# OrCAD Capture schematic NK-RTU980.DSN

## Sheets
1 System Block: size A; title: NK-980mini; rev: 1.0; company: nuvoTon Technology Corp.; note: System Block
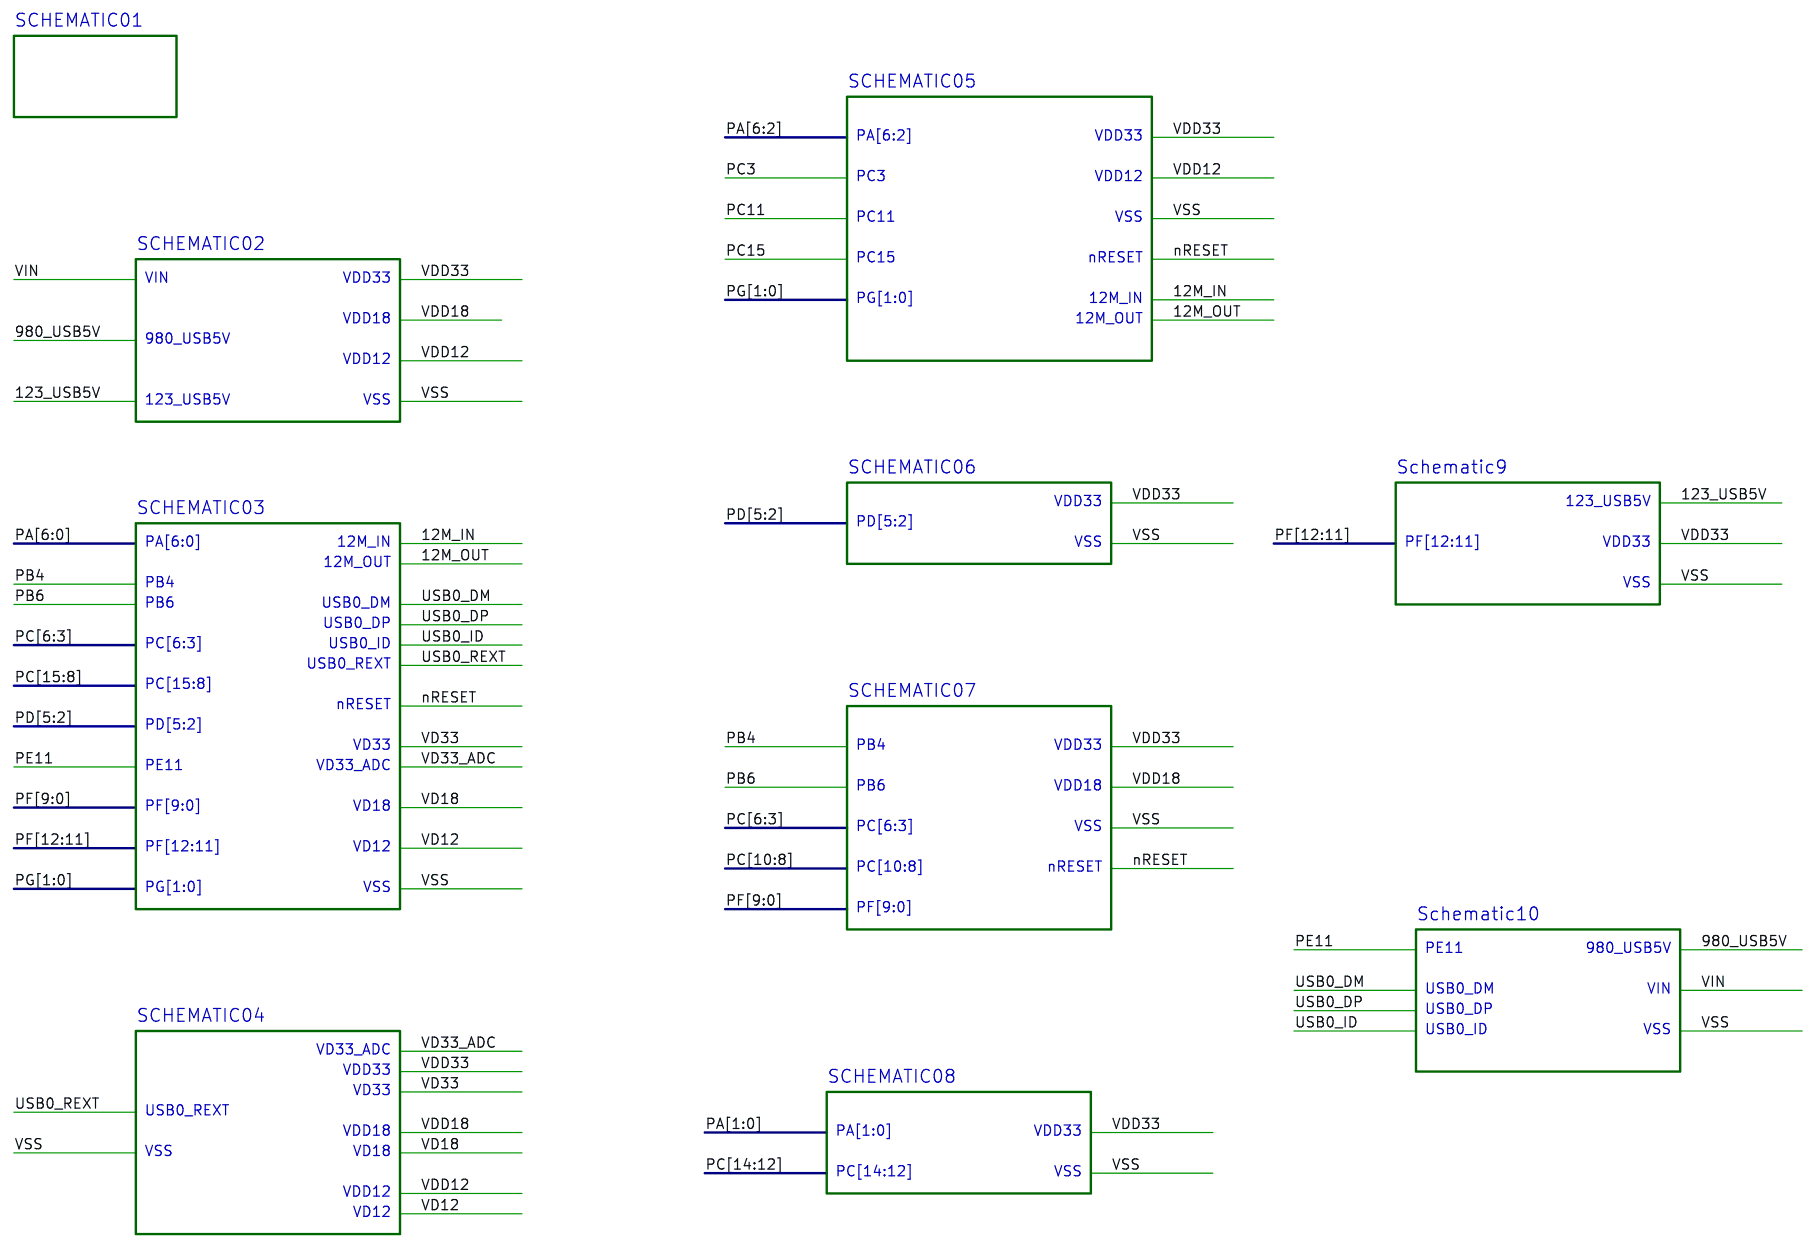
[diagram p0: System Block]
2 NUC980DR: size Custom; note: NUC980DR; block SCHEMATIC03
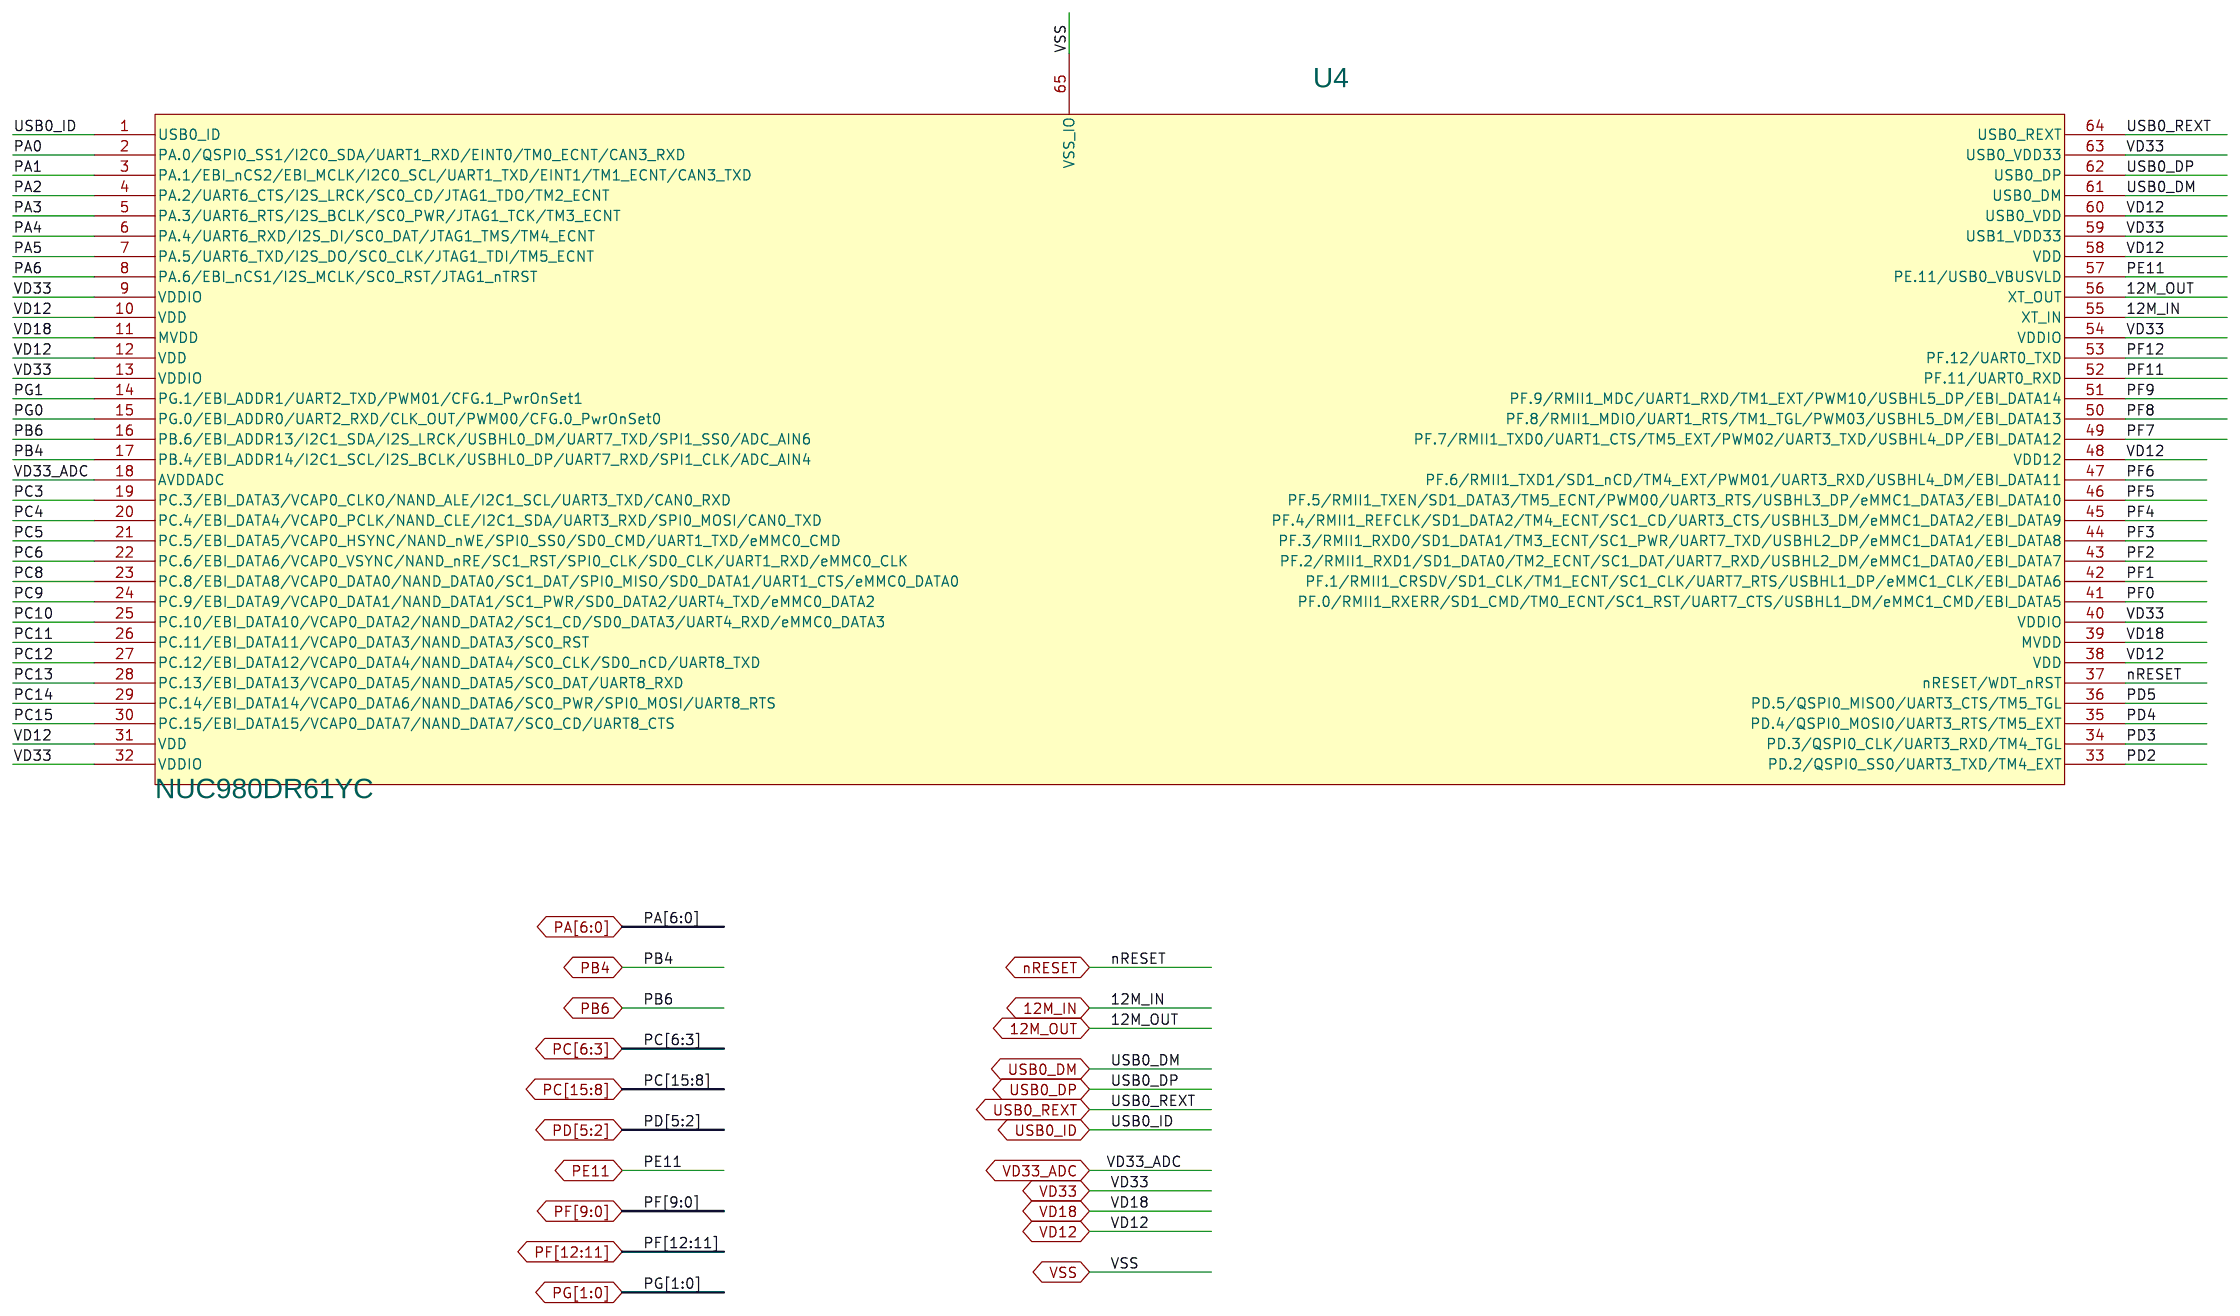
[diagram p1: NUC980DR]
3 NUC123ZD4AN0: size A; note: NUC123ZD4AN0; block Schematic9
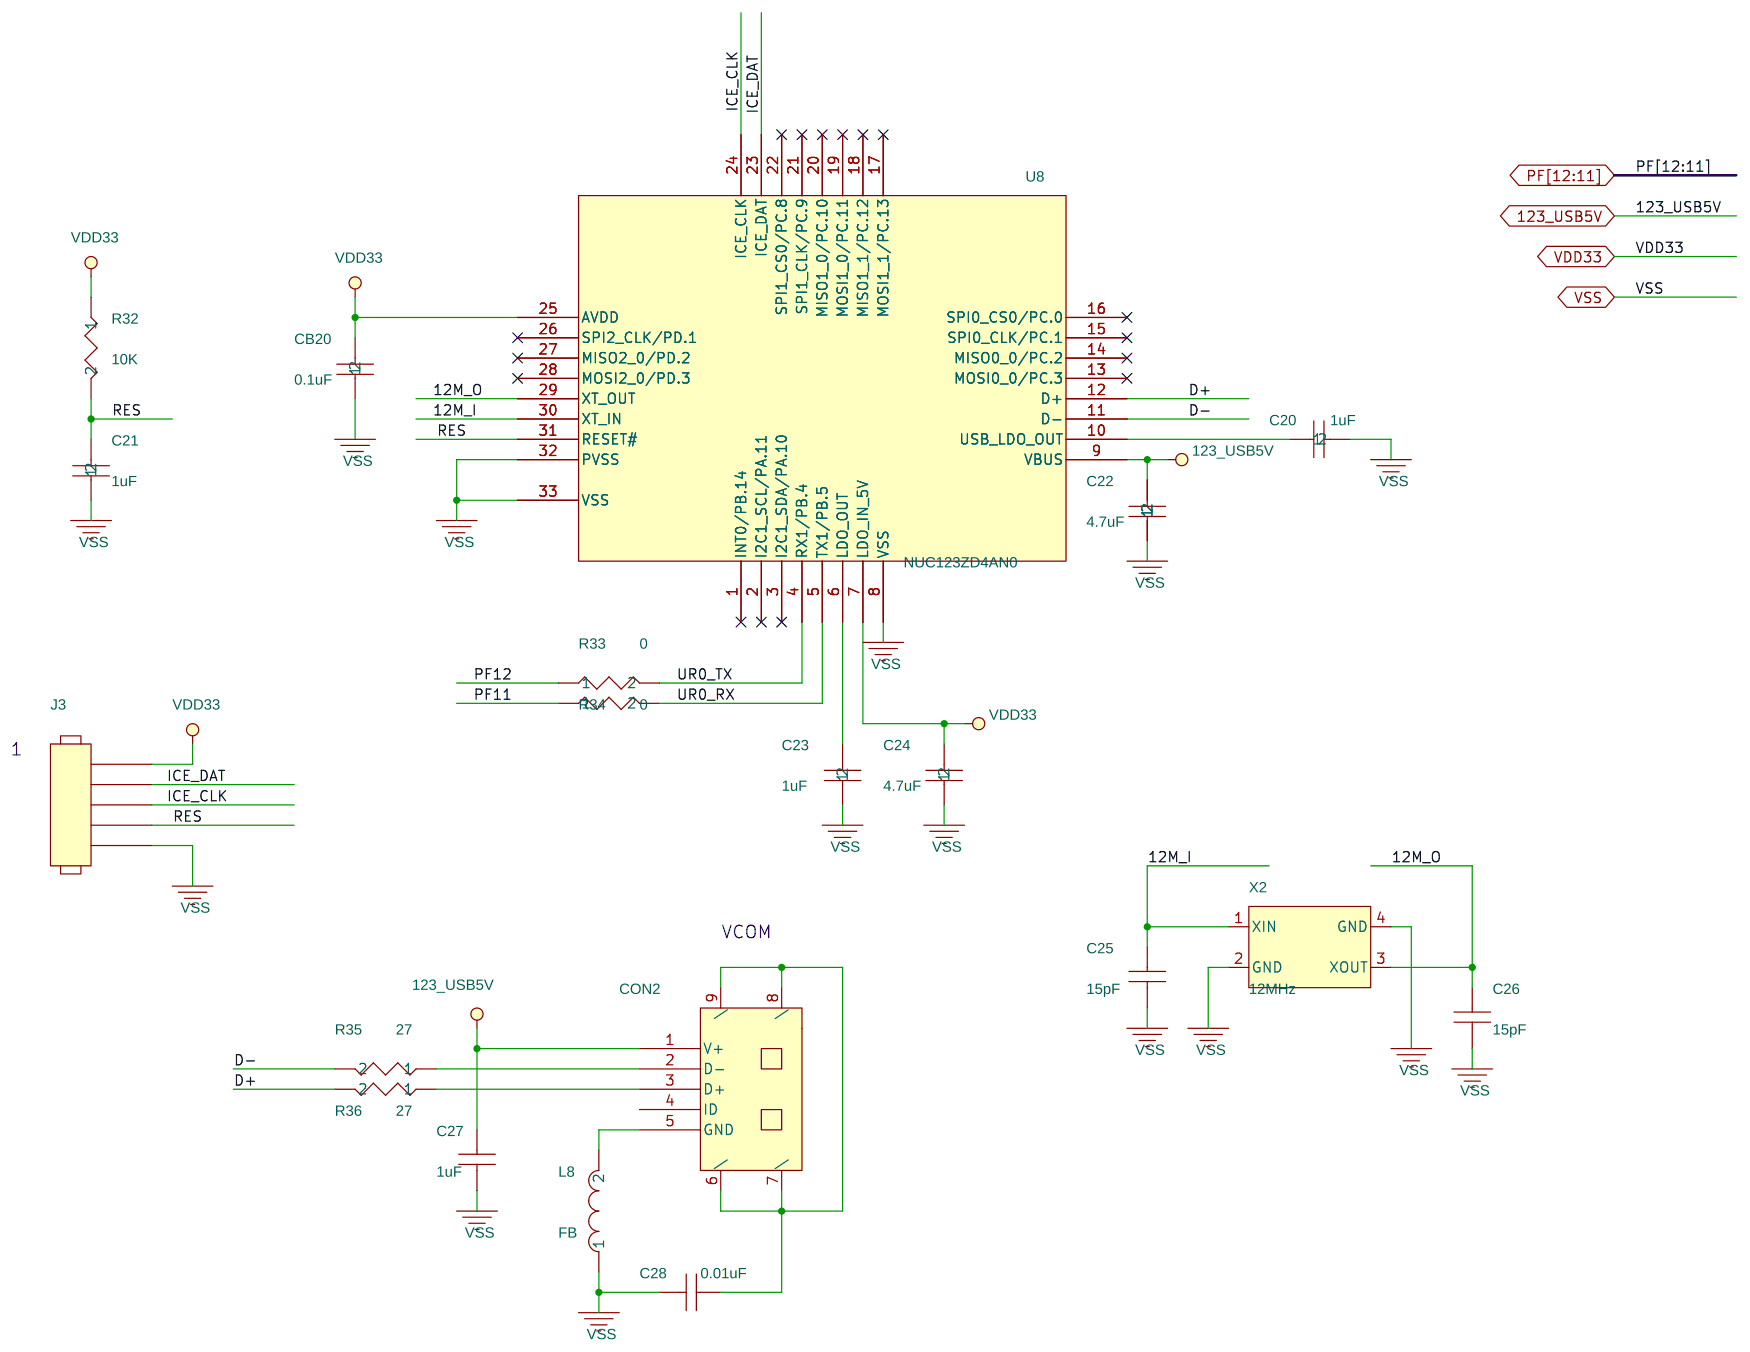
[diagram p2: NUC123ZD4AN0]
4 Setting, ICE, Reset, Debug: size A; note: Setting, ICE, Reset, Debug; block SCHEMATIC05
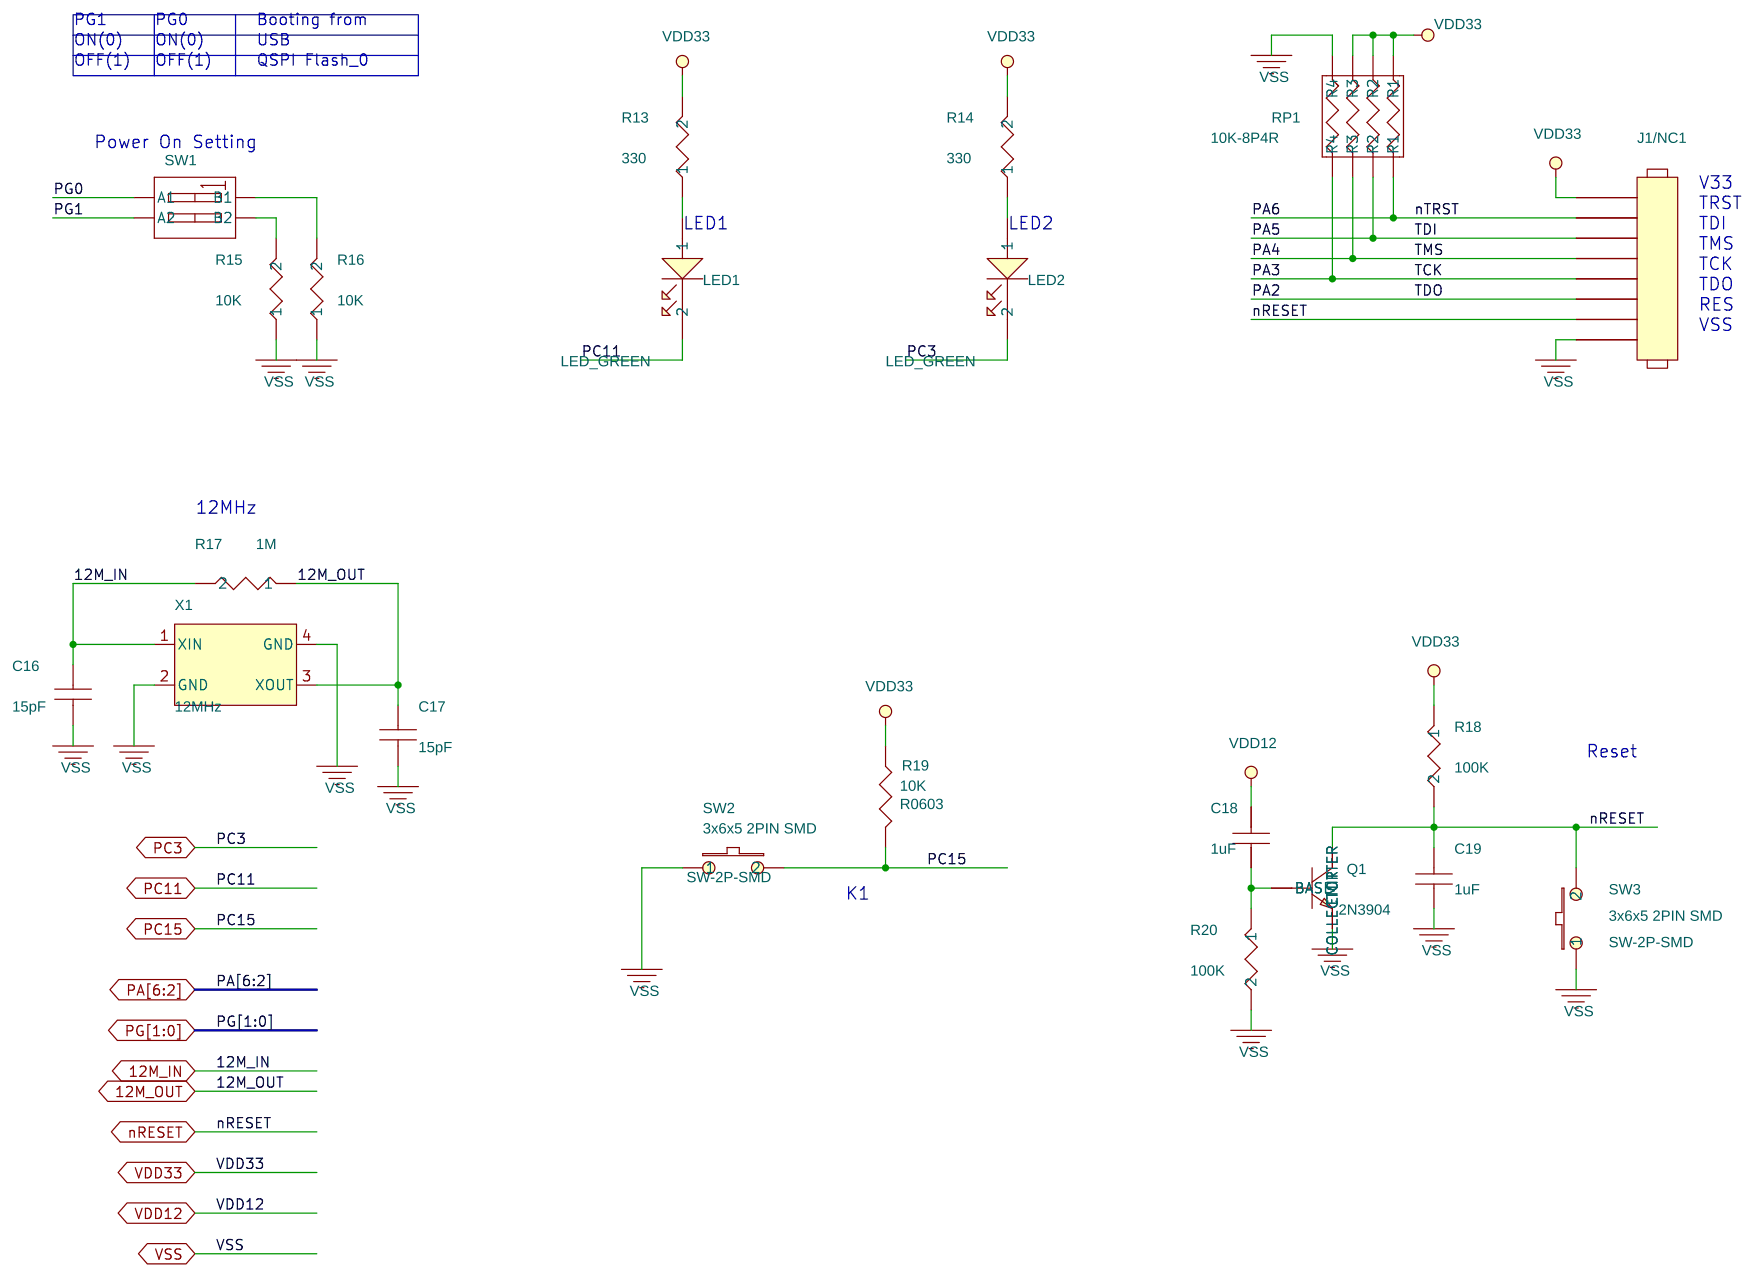
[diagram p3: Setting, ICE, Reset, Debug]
5 USB: size A; note: USB; block Schematic10
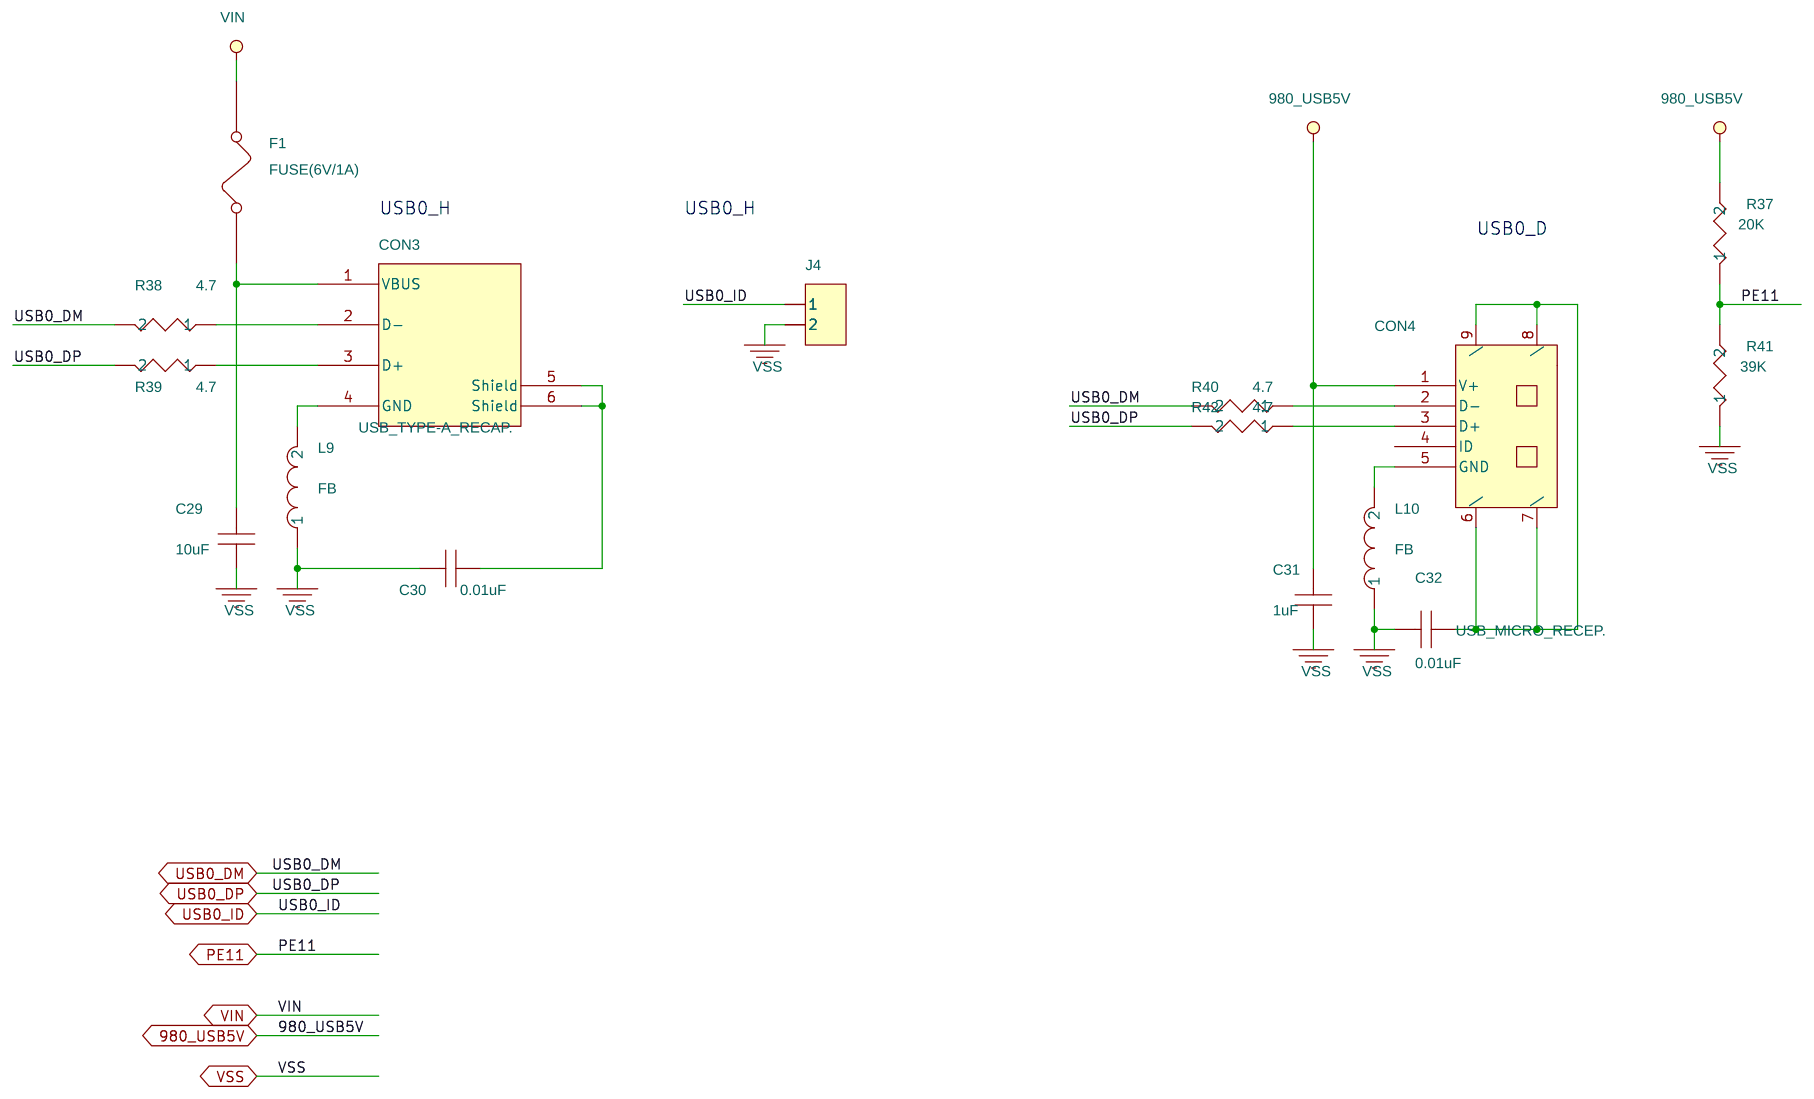
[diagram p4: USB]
6 Power Filter: size A; note: Power Filter; block SCHEMATIC04
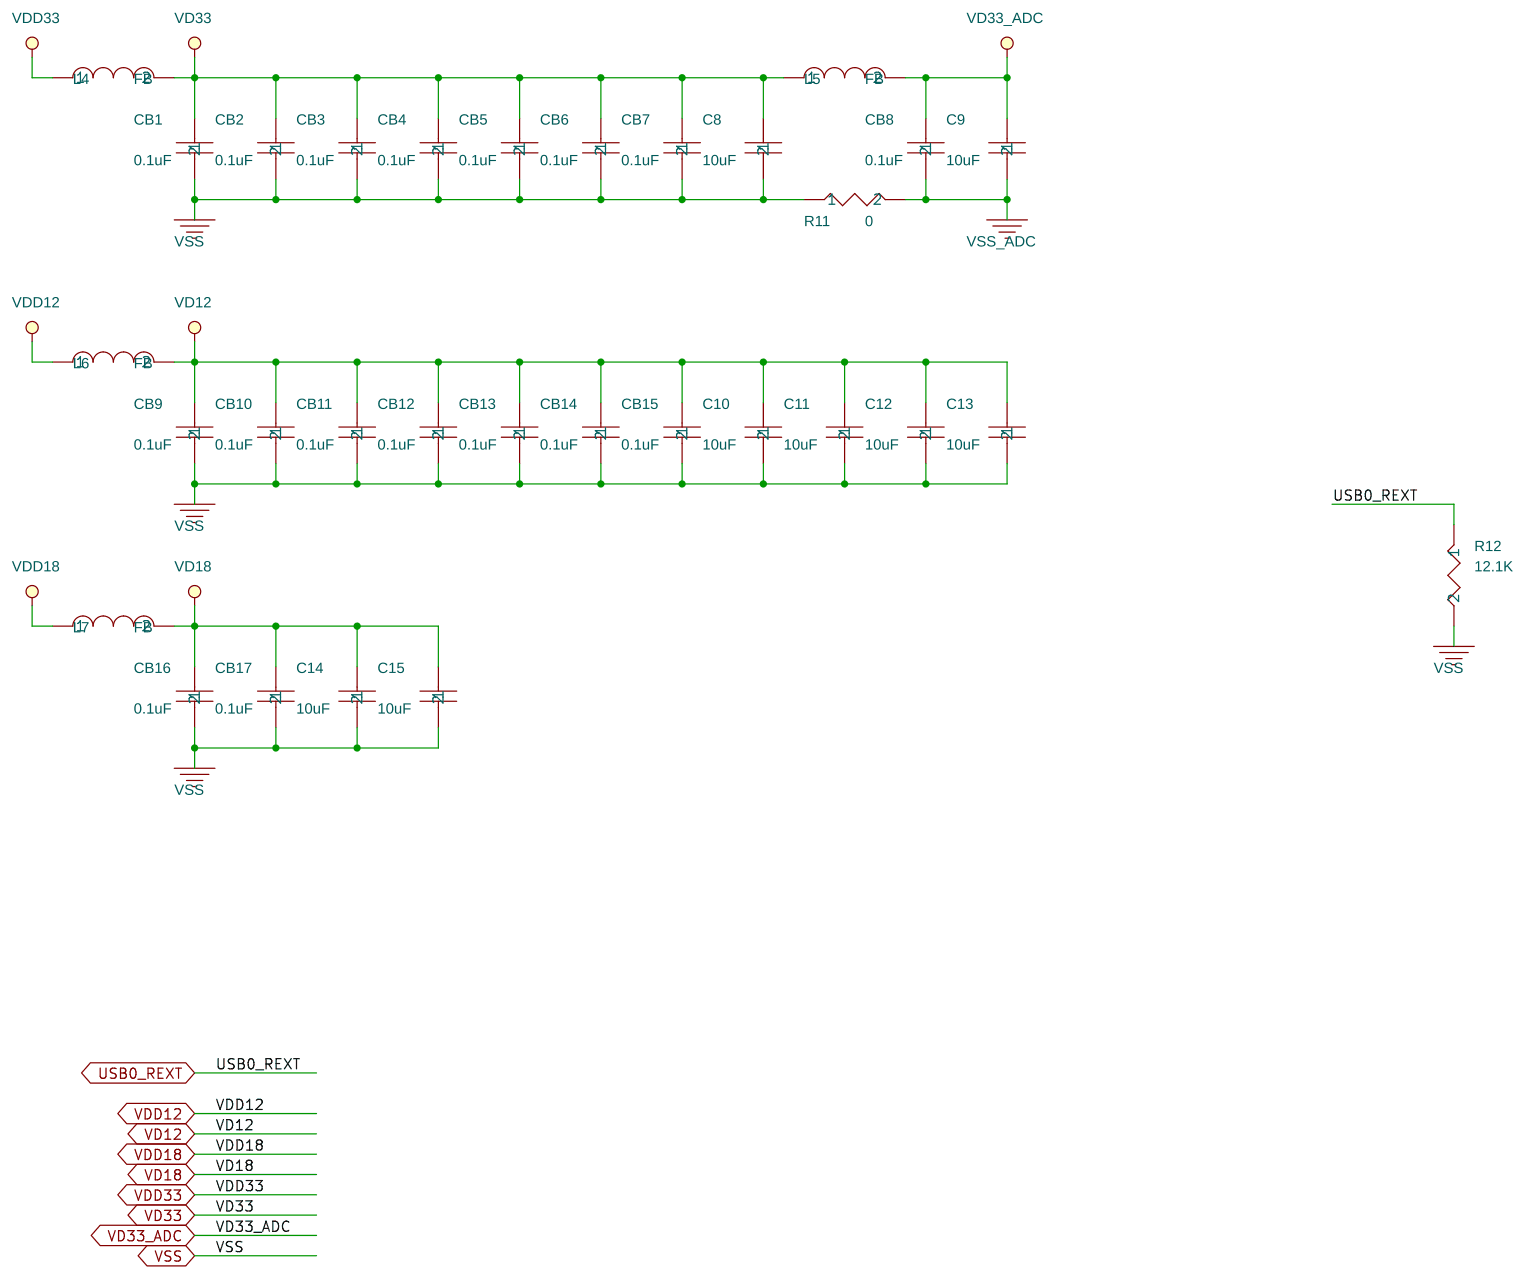
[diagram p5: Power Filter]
7 Ethernet: size A; note: Ethernet; block SCHEMATIC07
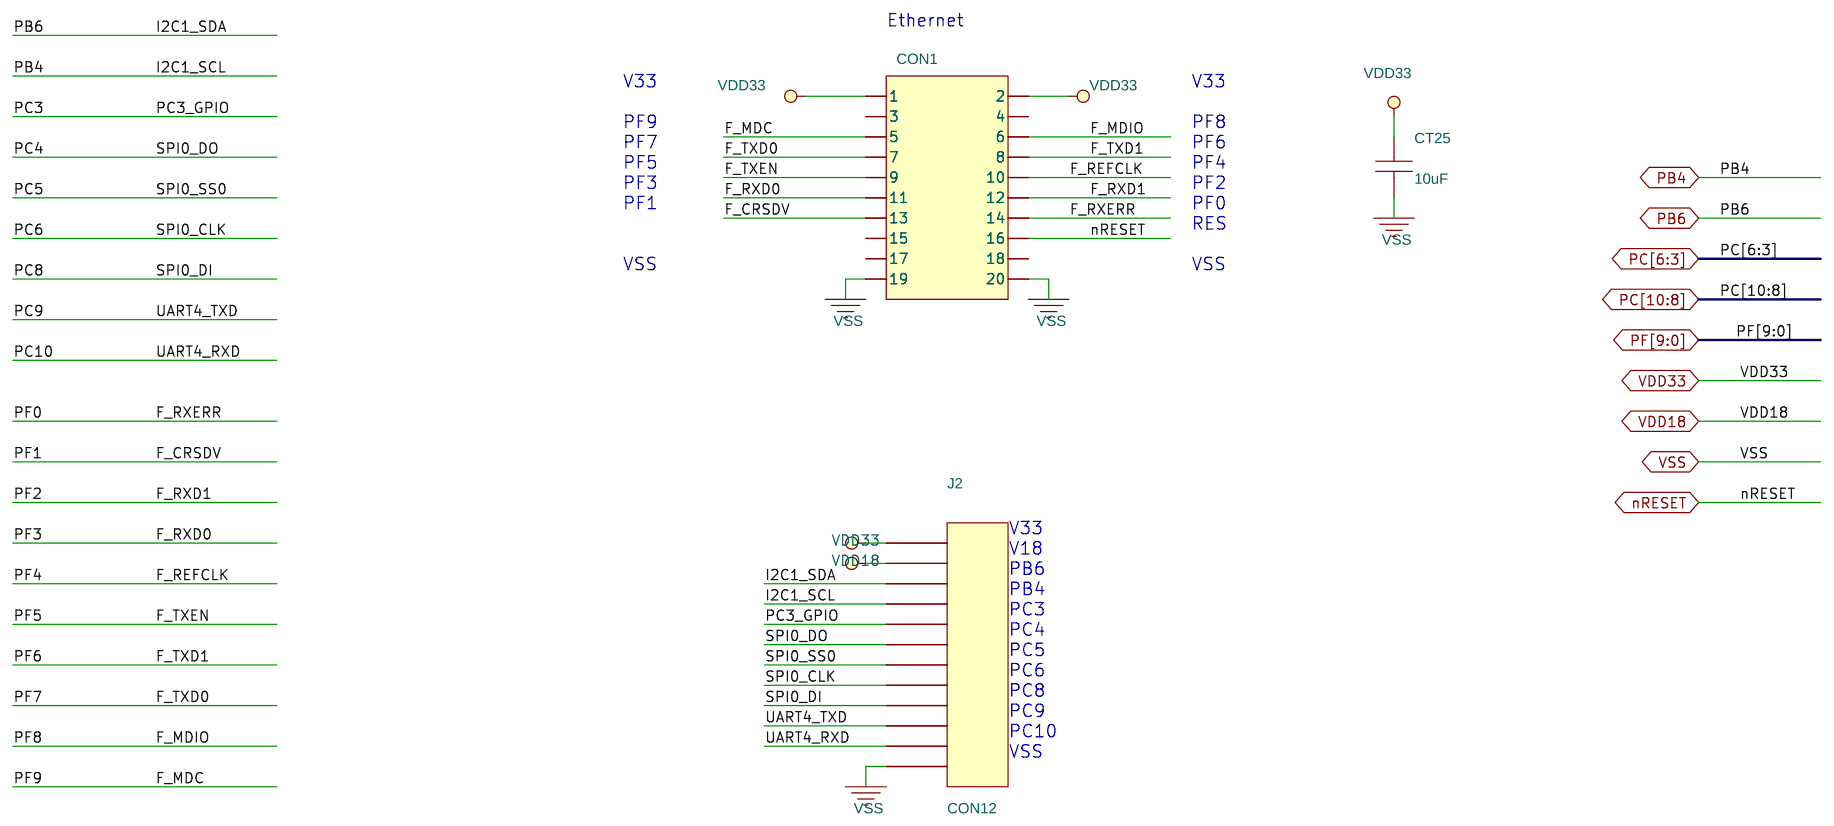
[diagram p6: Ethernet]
8 RS485/CAN: size A; note: RS485/CAN; block SCHEMATIC08
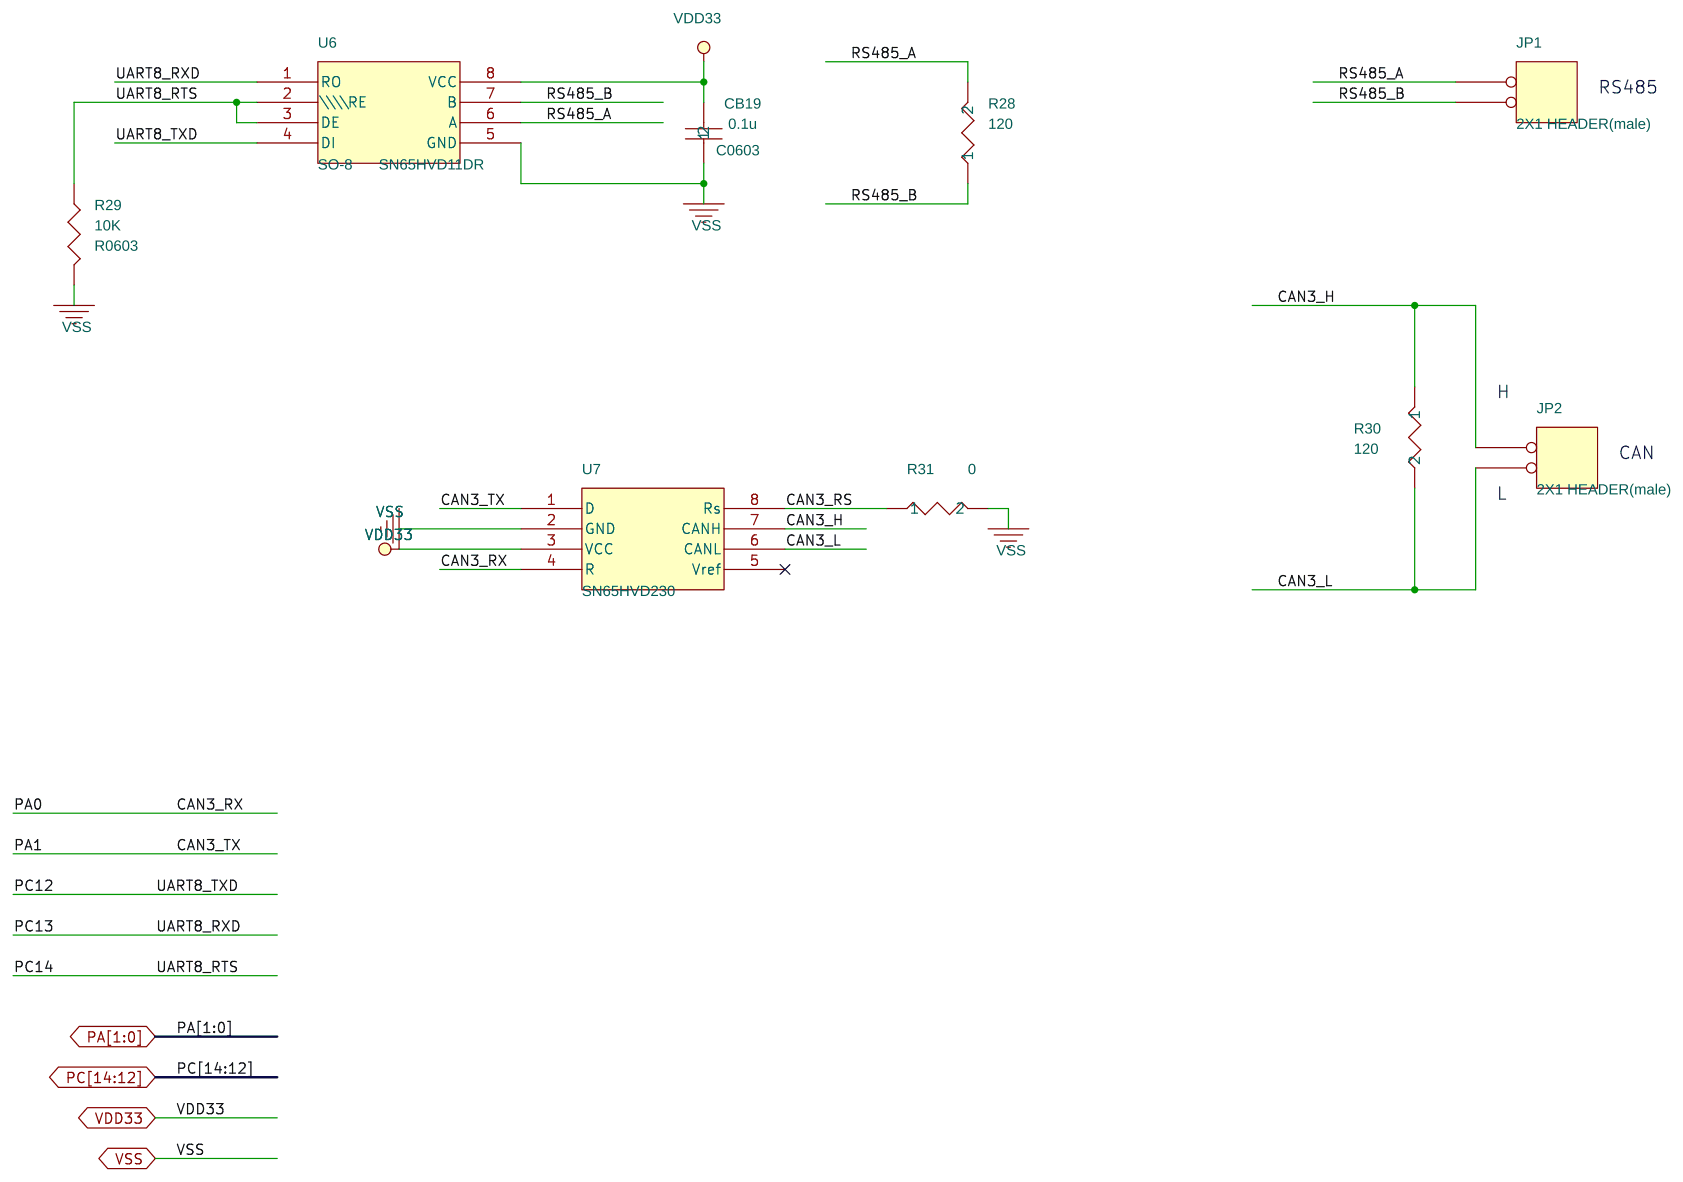
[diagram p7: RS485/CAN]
9 Memory: size A; note: Memory; block SCHEMATIC06
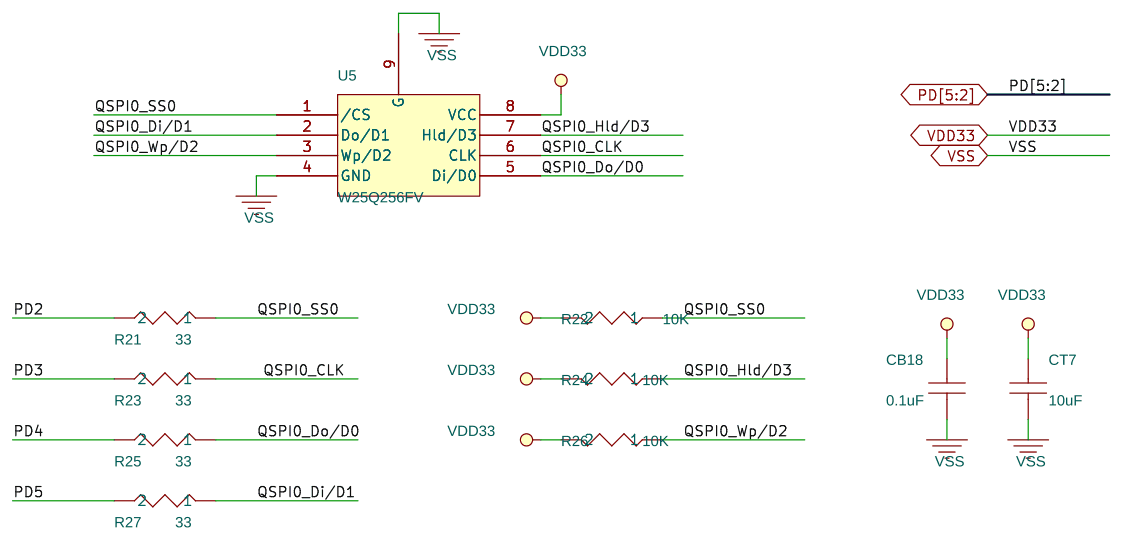
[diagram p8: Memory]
10 GPIO List: note: GPIO List
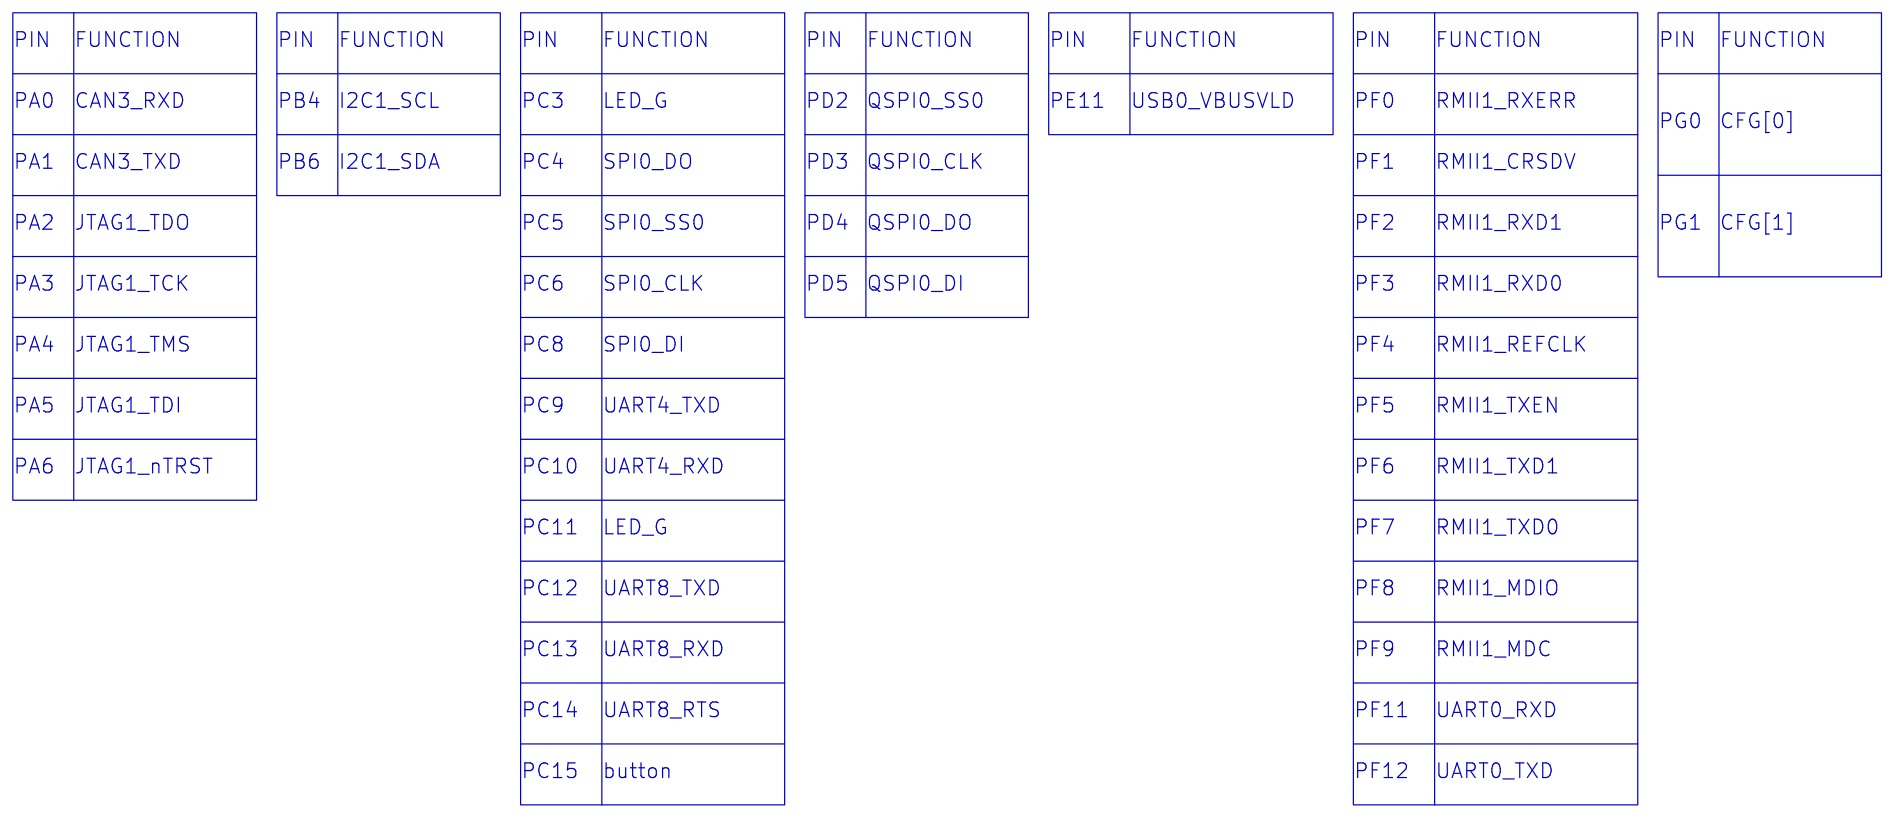
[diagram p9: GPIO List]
11 Power: size A; note: Power; block SCHEMATIC02
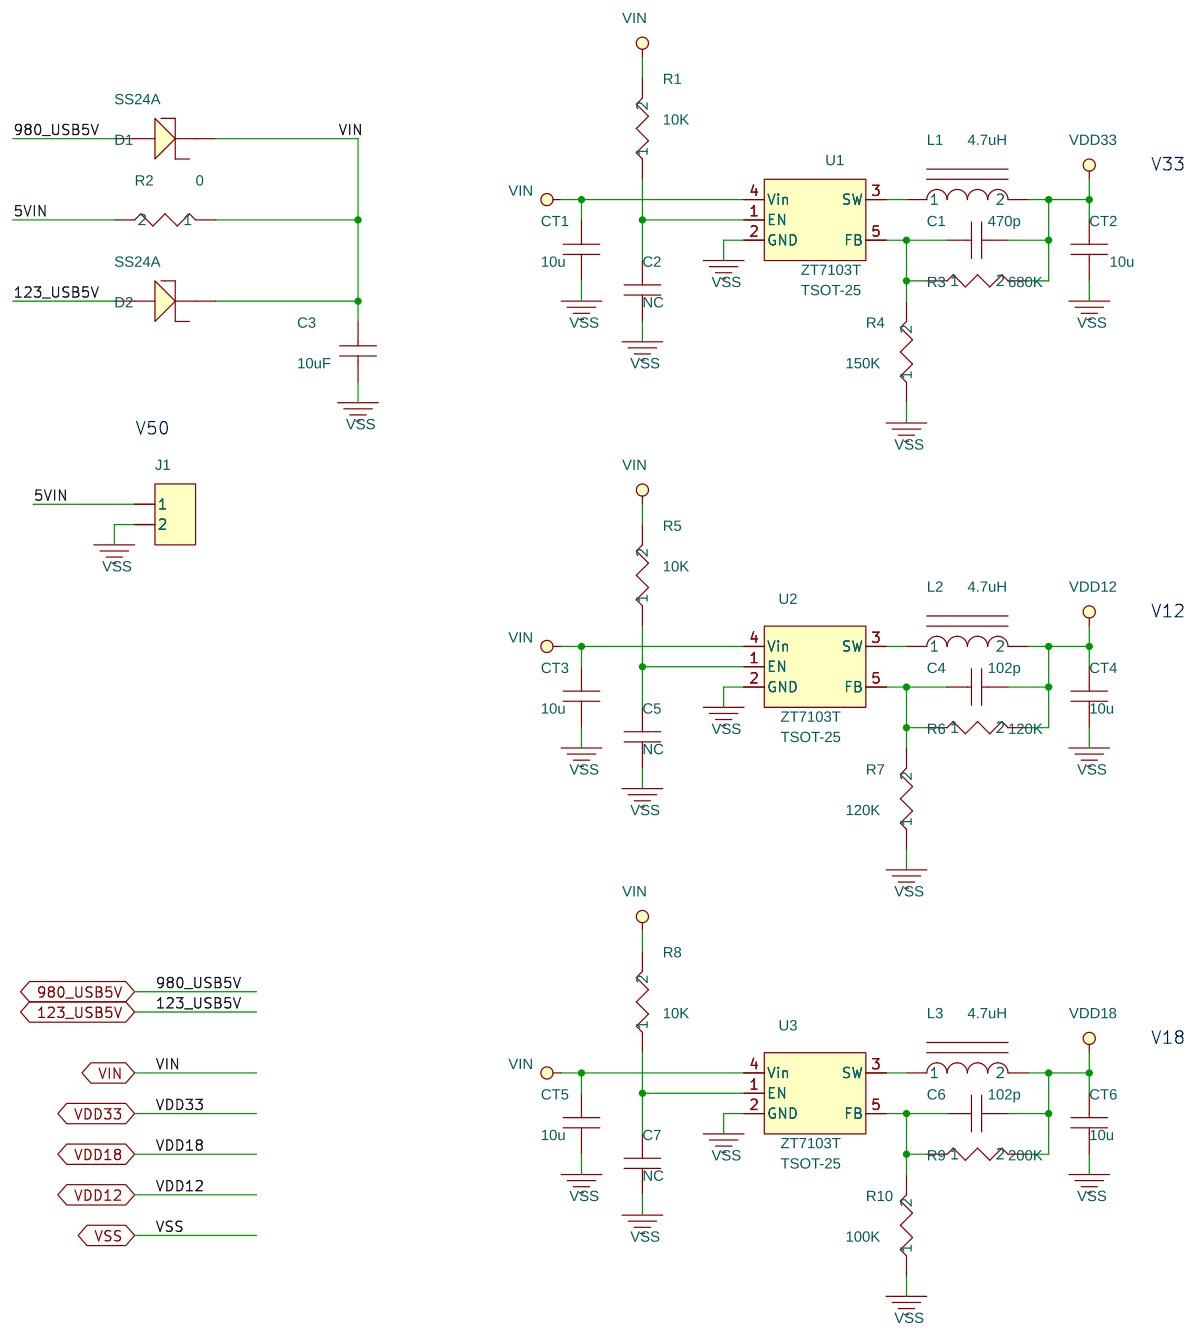
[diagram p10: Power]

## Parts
sheet Ethernet
CON1  RMII_PF  [Header_2x10_2.54mm]
CT25  10uF  [C0603]
J2  CON12  [Header_1x12_2.54mm]
sheet Memory
CB18  0.1uF  [C0603]
CT7  10uF  [C0603]
R21  33  [R0603]
R22  10K  [R0603]
R23  33  [R0603]
R24  10K  [R0603]
R25  33  [R0603]
R26  10K  [R0603]
R27  33  [R0603]
U5  W25Q256FV  [SOIC8_208_EP]
sheet NUC123ZD4AN0
C20  1uF  [C0603]
C21  1uF  [C0603]
C22  4.7uF  [C0603]
C23  1uF  [C0603]
C24  4.7uF  [C0603]
C25  15pF  [C0603]
C26  15pF  [C0603]
C27  1uF  [C0603]
C28  0.01uF  [C0603]
CB20  0.1uF  [C0603]
CON2  USB_MICRO_RECEP.  [MICRO_USB_AB_LS]
J3  HEADER5/2.54mm_M  [CON/5X1/2mm]
L8  FB  [0603]
R32  10K  [R0603]
R33  0  [R0603]
R34  0  [R0603]
R35  27  [R0603]
R36  27  [R0603]
U8  NUC123ZD4AN0  [QFN33_5X5]
X2  12MHz  [TXC7m-3.2x2.5mm]
sheet NUC980DR
U4  NUC980DR61YC  [TQFP-64]
sheet Power Filter
C8  10uF  [C0603]
C9  10uF  [C0603]
C10  10uF  [C0603]
C11  10uF  [C0603]
C12  10uF  [C0603]
C13  10uF  [C0603]
C14  10uF  [C0603]
C15  10uF  [C0603]
CB1  0.1uF  [C0603]
CB2  0.1uF  [C0603]
CB3  0.1uF  [C0603]
CB4  0.1uF  [C0603]
CB5  0.1uF  [C0603]
CB6  0.1uF  [C0603]
CB7  0.1uF  [C0603]
CB8  0.1uF  [C0603]
CB9  0.1uF  [C0603]
CB10  0.1uF  [C0603]
CB11  0.1uF  [C0603]
CB12  0.1uF  [C0603]
CB13  0.1uF  [C0603]
CB14  0.1uF  [C0603]
CB15  0.1uF  [C0603]
CB16  0.1uF  [C0603]
CB17  0.1uF  [C0603]
L4  FB  [0603]
L5  FB  [0603]
L6  FB  [0603]
L7  FB  [0603]
R11  0  [R0603]
R12  12.1K  [R0603]
sheet Power
C1  470p  [C0603]
C2  NC  [C0603]
C3  10uF  [C0603]
C4  102p  [C0603]
C5  NC  [C0603]
C6  102p  [C0603]
C7  NC  [C0603]
CT1  10u  [C0603]
CT2  10u  [C0603]
CT3  10u  [C0603]
CT4  10u  [C0603]
CT5  10u  [C0603]
CT6  10u  [C0603]
D1  SS24A  [403A-03]
D2  SS24A  [403A-03]
J1  USB  [Header_2x1_2.54mm]
L1  4.7uH  [SMTDR43]
L2  4.7uH  [SMTDR43]
L3  4.7uH  [SMTDR43]
R1  10K  [R0603]
R2  0  [R0603]
R3  680K  [R0603]
R4  150K  [R0603]
R5  10K  [R0603]
R6  120K  [R0603]
R7  120K  [R0603]
R8  10K  [R0603]
R9  200K  [R0603]
R10  100K  [R0603]
U1  ZT7103T  [TSOT-25]
U2  ZT7103T  [TSOT-25]
U3  ZT7103T  [TSOT-25]
sheet RS485/CAN
CB19  0.1u  [C0603]
JP1  2X1 HEADER(male)  [Header_2x1_2.54mm]
JP2  2X1 HEADER(male)  [Header_2x1_2.54mm]
R28  120  [R0603]
R29  10K  [R0603]
R30  120  [R0603]
R31  0  [R0603]
U6  SN65HVD11DR  [SO-8]
U7  SN65HVD230  [SO-8-1.27X5.4M]
sheet Setting, ICE, Reset, Debug
C16  15pF  [C0603]
C17  15pF  [C0603]
C18  1uF  [C0603]
C19  1uF  [C0603]
J1/NC1  HEADER 8  [HEADER8/2MM_M]
LED1  LED_GREEN  [LED_0805]
LED2  LED_GREEN  [LED_0805]
Q1  2N3904  [SOT-23BEC]
R13  330  [R0603]
R14  330  [R0603]
R15  10K  [R0603]
R16  10K  [R0603]
R17  1M  [R0603]
R18  100K  [R0603]
R19  10K  [R0603]
R20  100K  [R0603]
RP1  10K-8P4R  [8P4RA]
SW1  DIP-SW2  [DIPSWx2_2.54mm]
SW2  3x6x5 2PIN SMD  [SW-2P-SMD]
SW3  3x6x5 2PIN SMD  [SW-2P-SMD]
X1  12MHz  [TXC7m-3.2x2.5mm]
sheet USB
C29  10uF  [C0603]
C30  0.01uF  [C0603]
C31  1uF  [C0603]
C32  0.01uF  [C0603]
CON3  USB_TYPE-A_RECAP.  [USB4P]
CON4  USB_MICRO_RECEP.  [MICRO_USB_AB_LS]
F1  FUSE(6V/1A)  [R0603]
J4  USB  [Header_2x1_2.54mm]
L9  FB  [0603]
L10  FB  [0603]
R37  20K  [R0603]
R38  4.7  [R0603]
R39  4.7  [R0603]
R40  4.7  [R0603]
R41  39K  [R0603]
R42  4.7  [R0603]

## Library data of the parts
CON1 = CON20A
C4 C19 C25 C29 CB18 CT25 = CAP_NP_v2
J2 = CON12
C5 C16 C26 C32 CT7 = CAP_NP_v2_1
R1 R11 R16 R21 R33 R38 = R
R5 R13 R22 R36 R37 = R_3
R3 R12 R17 R23 R30 R34 R41 = R_1
R4 R14 R24 = R_6
R6 R15 R25 R32 R42 = R_4
R2 R18 R26 R35 R39 = R_2
R10 R20 R27 R40 = R_5
U5 = W55X10_3
C20 = CAP-C_4: Package: 0603
C21 = CAP-C_5: Package: 0603
C22 = CAP-C_3: Package: 0603
C23 CB19 = CAP-C: Package: 0603
C24 = CAP-C_2: Package: 0603
C17 C27 C30 CT4 = CAP_NP_v2_2
C18 C28 C31 CT5 = CAP_NP_v2_3
CB20 = CAP-C_1: Package: 0603
CON2 CON4 = USB_Type_B_0
J3 = HEADER_5
L6 L8 L10 = INDUCTOR
U8 = NUC101_QFN_0
X1 X2 = Crystal_SMD_2
U4 = NUC970_18
C8 = CAP-B_22
C9 = CAP-B_1
C10 = CAP-B_6
C11 = CAP-B_10
C12 = CAP-B_14
C13 = CAP-B_18
C14 = CAP-B_12
C15 = CAP-B_16
CB1 = CAP-B_13
CB2 = CAP-B_8
CB3 = CAP-B_11
CB4 = CAP-B_15
CB5 = CAP-B_17
CB6 = CAP-B_19
CB7 = CAP-B_21
CB8 = CAP-B_20
CB9 = CAP-B_7
CB10 = CAP-B_23
CB11 = CAP-B
CB12 = CAP-B_2
CB13 = CAP-B_3
CB14 = CAP-B_4
CB15 = CAP-B_5
CB16 = CAP-B_24
CB17 = CAP-B_9
L4 = INDUCTOR_3
L5 = INDUCTOR_2
L7 L9 = INDUCTOR_1
C1 = CAP_NP_v2_6
C2 = CAP_NP_v2_8
C3 = CAP_NP_v2_9
C6 = CAP_NP_v2_11
C7 = CAP_NP_v2_7
CT1 = CAP_NP_v2_10
CT2 = CAP_NP_v2_5
CT3 = CAP_NP_v2_4
CT6 = CAP_NP_v2_12
D1 D2 = ZENAR_0: Package: D
J1 J4 = CON2
L1 = INDUCTOR_IRON_1
L2 = INDUCTOR_IRON_2
L3 = INDUCTOR_IRON
R7 = R_8
R8 = R_7
R9 = R_9
U1-U3 = ZT7103S_0
JP1 JP2 = HEADER_2
R28 = R_2: Package: 0603
R19 R29 = R_0: Package: 0603
R31 = R: Package: R0402
U6 = ADM232_1: Package: DIP16\SO
U7 = SN65HVD230: Package: SO-8
J1/NC1 = HEADER_8_0
LED1 = LED_0_1
LED2 = LED_0
Q1 = NPN
RP1 = R-PACK8_0
SW1 = SW_DIP-2_0
SW2 = SW_PUSHBUTTON_0_1
SW3 = SW_PUSHBUTTON_0
CON3 = USB_type_A_connector
F1 = FUSE

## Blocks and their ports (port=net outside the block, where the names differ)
SCHEMATIC01 = schematic SCHEMATIC01, on sheet System Block: no ports
SCHEMATIC08 = schematic SCHEMATIC08, on sheet System Block: PA[1:0], VDD33, VSS, PC[14:12]
SCHEMATIC04 = schematic SCHEMATIC04, on sheet System Block: USB0_REXT, VDD12, VD18, VD33, VSS, VD12, VDD18, VDD33, VD33_ADC
SCHEMATIC02 = schematic SCHEMATIC02, on sheet System Block: 980_USB5V, VDD33, VDD18, VDD12, VSS, 123_USB5V, VIN
SCHEMATIC05 = schematic SCHEMATIC05, on sheet System Block: VDD33, VSS, PA[6:2], 12M_IN, 12M_OUT, nRESET, VDD12, PG[1:0], PC11, PC15, PC3
SCHEMATIC07 = schematic SCHEMATIC07, on sheet System Block: PF[9:0], VDD33, VSS, nRESET, PC[6:3], PB4, PB6, VDD18, PC[10:8]
Schematic10 = schematic SCHEMATIC10, on sheet System Block: 980_USB5V, PE11, VSS, USB0_DP, USB0_DM, VIN, USB0_ID
SCHEMATIC06 = schematic SCHEMATIC06, on sheet System Block: VDD33, VSS, PD[5:2]
SCHEMATIC03 = schematic SCHEMATIC03, on sheet System Block: PE11, PB4, PB6, PC[15:8], VD12, VD18, VD33, VSS, PG[1:0], VD33_ADC, USB0_DM, USB0_DP, USB0_REXT, nRESET, PA[6:0], PC[6:3], PD[5:2], PF[9:0], PF[12:11], 12M_IN, 12M_OUT, USB0_ID
Schematic9 = schematic SCHEMATIC09, on sheet System Block: PF[12:11], VDD33, VSS, 123_USB5V

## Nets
SCHEMATIC02/5VIN: J1.1 R2.2
VDD12: C4.2 C18.2 CT4.1 L2.2 L6.1 R6.2
VDD18: C6.2 CT6.1 J2.2 L3.2 L7.1 R9.2
VDD33: C1.2 C24.2 CB18.1 CB19.2 CB20.2 CON1.1 CON1.2 CT2.1 CT7.1 CT25.1 J1/NC1.1 J2.1 J3.1 L1.2 L4.1 R3.2 R13.2 R14.2 R18.1 R19.2 R22.2 R24.2 R26.2 R32.1 RP1.1(R1) RP1.3(R2) RP1.5(R3) U5.8(VCC) U6.8(VCC) U7.3(VCC) U8.7(LDO_IN_5V) U8.25(AVDD)
VIN: C3.1 CT1.1 CT3.1 CT5.1 D1.2 D2.2 F1.2 R1.2 R2.1 R5.2 R8.2 U1.4(Vin) U2.4(Vin) U3.4(Vin)
VSS: C2.2 C3.2 C5.2 C7.2 C8.2 C10.2 C11.2 C12.2 C13.2 C14.2 C15.2 C16.2 C17.2 C19.1 C20.2 C21.1 C22.1 C23.1 C24.1 C25.2 C26.2 C27.2 C28.2 C29.1 C30.2 C31.1 C32.2 CB1.2 CB2.2 CB3.2 CB4.2 CB5.2 CB6.2 CB7.2 CB9.2 CB10.2 CB11.2 CB12.2 CB13.2 CB14.2 CB15.2 CB16.2 CB17.2 CB18.2 CB19.1 CB20.1 CON1.19 CON1.20 CT1.2 CT2.2 CT3.2 CT4.2 CT5.2 CT6.2 CT7.2 CT25.2 J1.2 J1/NC1.8 J2.12 J3.5 J4.2 L8.1 L9.1 L10.1 Q1.EMITTER R4.1 R7.1 R10.1 R11.1 R12.2 R15.1 R16.1 R20.2 R29.2 R31.2 R41.1 RP1.7(R4) SW2.1 SW3.1 U1.2(GND) U2.2(GND) U3.2(GND) U4.65(VSS_IO) U5.4(GND) U5.9(G) U6.5(GND) U7.2(GND) U8.8(VSS) U8.32(PVSS) U8.33(VSS) X1.2(GND) X1.4(GND) X2.2(GND) X2.4(GND)
VSS_ADC: C9.2 CB8.2 R11.2
12M_IN: C16.1 R17.2 U4.55(XT_IN) X1.1(XIN)
12M_OUT: C17.1 R17.1 U4.56(XT_OUT) X1.3(XOUT)
123_USB5V: C22.2 C27.1 CON2.1(V+) D2.1 U8.9(VBUS)
980_USB5V: C31.2 CON4.1(V+) D1.1 R37.2
nRESET: C19.2 CON1.16 J1/NC1.7 Q1.COLLECTOR R18.2 SW3.2 U4.37(nRESET/WDT_nRST)
PA0: U4.2(PA.0/QSPI0_SS1/I2C0_SDA/UART1_RXD/EINT0/TM0_ECNT/CAN3_RXD) U7.4(R)
PA1: U4.3(PA.1/EBI_nCS2/EBI_MCLK/I2C0_SCL/UART1_TXD/EINT1/TM1_ECNT/CAN3_TXD) U7.1(D)
PA2: J1/NC1.6 U4.4(PA.2/UART6_CTS/I2S_LRCK/SC0_CD/JTAG1_TDO/TM2_ECNT)
PA3: J1/NC1.5 RP1.8(R4) U4.5(PA.3/UART6_RTS/I2S_BCLK/SC0_PWR/JTAG1_TCK/TM3_ECNT)
PA4: J1/NC1.4 RP1.6(R3) U4.6(PA.4/UART6_RXD/I2S_DI/SC0_DAT/JTAG1_TMS/TM4_ECNT)
PA5: J1/NC1.3 RP1.4(R2) U4.7(PA.5/UART6_TXD/I2S_DO/SC0_CLK/JTAG1_TDI/TM5_ECNT)
PA6: J1/NC1.2 RP1.2(R1) U4.8(PA.6/EBI_nCS1/I2S_MCLK/SC0_RST/JTAG1_nTRST)
PB4: J2.4 U4.17(PB.4/EBI_ADDR14/I2C1_SCL/I2S_BCLK/USBHL0_DP/UART7_RXD/SPI1_CLK/ADC_AIN4)
PB6: J2.3 U4.16(PB.6/EBI_ADDR13/I2C1_SDA/I2S_LRCK/USBHL0_DM/UART7_TXD/SPI1_SS0/ADC_AIN6)
PC3: J2.5 LED2.2 U4.19(PC.3/EBI_DATA3/VCAP0_CLKO/NAND_ALE/I2C1_SCL/UART3_TXD/CAN0_RXD)
PC4: J2.6 U4.20(PC.4/EBI_DATA4/VCAP0_PCLK/NAND_CLE/I2C1_SDA/UART3_RXD/SPI0_MOSI/CAN0_TXD)
PC5: J2.7 U4.21(PC.5/EBI_DATA5/VCAP0_HSYNC/NAND_nWE/SPI0_SS0/SD0_CMD/UART1_TXD/eMMC0_CMD)
PC6: J2.8 U4.22(PC.6/EBI_DATA6/VCAP0_VSYNC/NAND_nRE/SC1_RST/SPI0_CLK/SD0_CLK/UART1_RXD/eMMC0_CLK)
PC8: J2.9 U4.23(PC.8/EBI_DATA8/VCAP0_DATA0/NAND_DATA0/SC1_DAT/SPI0_MISO/SD0_DATA1/UART1_CTS/eMMC0_DATA0)
PC9: J2.10 U4.24(PC.9/EBI_DATA9/VCAP0_DATA1/NAND_DATA1/SC1_PWR/SD0_DATA2/UART4_TXD/eMMC0_DATA2)
PC10: J2.11 U4.25(PC.10/EBI_DATA10/VCAP0_DATA2/NAND_DATA2/SC1_CD/SD0_DATA3/UART4_RXD/eMMC0_DATA3)
PC11: LED1.2 U4.26(PC.11/EBI_DATA11/VCAP0_DATA3/NAND_DATA3/SC0_RST)
PC12: U4.27(PC.12/EBI_DATA12/VCAP0_DATA4/NAND_DATA4/SC0_CLK/SD0_nCD/UART8_TXD) U6.4(DI)
PC13: U4.28(PC.13/EBI_DATA13/VCAP0_DATA5/NAND_DATA5/SC0_DAT/UART8_RXD) U6.1(RO)
PC14: R29.1 U4.29(PC.14/EBI_DATA14/VCAP0_DATA6/NAND_DATA6/SC0_PWR/SPI0_MOSI/UART8_RTS) U6.2(\\\\RE) U6.3(DE)
PC15: R19.1 SW2.2 U4.30(PC.15/EBI_DATA15/VCAP0_DATA7/NAND_DATA7/SC0_CD/UART8_CTS)
PD2: R21.2 U4.33(PD.2/QSPI0_SS0/UART3_TXD/TM4_EXT)
PD3: R23.2 U4.34(PD.3/QSPI0_CLK/UART3_RXD/TM4_TGL)
PD4: R25.2 U4.35(PD.4/QSPI0_MOSI0/UART3_RTS/TM5_EXT)
PD5: R27.2 U4.36(PD.5/QSPI0_MISO0/UART3_CTS/TM5_TGL)
PE11: R37.1 R41.2 U4.57(PE.11/USB0_VBUSVLD)
PF0: CON1.14 U4.41(PF.0/RMII1_RXERR/SD1_CMD/TM0_ECNT/SC1_RST/UART7_CTS/USBHL1_DM/eMMC1_CMD/EBI_DATA5)
PF1: CON1.13 U4.42(PF.1/RMII1_CRSDV/SD1_CLK/TM1_ECNT/SC1_CLK/UART7_RTS/USBHL1_DP/eMMC1_CLK/EBI_DATA6)
PF2: CON1.12 U4.43(PF.2/RMII1_RXD1/SD1_DATA0/TM2_ECNT/SC1_DAT/UART7_RXD/USBHL2_DM/eMMC1_DATA0/EBI_DATA7)
PF3: CON1.11 U4.44(PF.3/RMII1_RXD0/SD1_DATA1/TM3_ECNT/SC1_PWR/UART7_TXD/USBHL2_DP/eMMC1_DATA1/EBI_DATA8)
PF4: CON1.10 U4.45(PF.4/RMII1_REFCLK/SD1_DATA2/TM4_ECNT/SC1_CD/UART3_CTS/USBHL3_DM/eMMC1_DATA2/EBI_DATA9)
PF5: CON1.9 U4.46(PF.5/RMII1_TXEN/SD1_DATA3/TM5_ECNT/PWM00/UART3_RTS/USBHL3_DP/eMMC1_DATA3/EBI_DATA10)
PF6: CON1.8 U4.47(PF.6/RMII1_TXD1/SD1_nCD/TM4_EXT/PWM01/UART3_RXD/USBHL4_DM/EBI_DATA11)
PF7: CON1.7 U4.49(PF.7/RMII1_TXD0/UART1_CTS/TM5_EXT/PWM02/UART3_TXD/USBHL4_DP/EBI_DATA12)
PF8: CON1.6 U4.50(PF.8/RMII1_MDIO/UART1_RTS/TM1_TGL/PWM03/USBHL5_DM/EBI_DATA13)
PF9: CON1.5 U4.51(PF.9/RMII1_MDC/UART1_RXD/TM1_EXT/PWM10/USBHL5_DP/EBI_DATA14)
PF11: R34.1 U4.52(PF.11/UART0_RXD)
PF12: R33.1 U4.53(PF.12/UART0_TXD)
PG0: SW1.1(A1) U4.15(PG.0/EBI_ADDR0/UART2_RXD/CLK_OUT/PWM00/CFG.0_PwrOnSet0)
PG1: SW1.2(A2) U4.14(PG.1/EBI_ADDR1/UART2_TXD/PWM01/CFG.1_PwrOnSet1)
SCHEMATIC06/QSPI0_CLK: R23.1 U5.6(CLK)
SCHEMATIC06/QSPI0_Di/D1: R27.1 U5.2(Do/D1)
SCHEMATIC06/QSPI0_Do/D0: R25.1 U5.5(Di/D0)
SCHEMATIC06/QSPI0_Hld/D3: R24.1 U5.7(Hld/D3)
SCHEMATIC06/QSPI0_SS0: R21.1 R22.1 U5.1(/CS)
SCHEMATIC06/QSPI0_Wp/D2: R26.1 U5.3(Wp/D2)
SCHEMATIC08/CAN3_H: JP2.1 R30.1 U7.7(CANH)
SCHEMATIC08/CAN3_L: JP2.2 R30.2 U7.6(CANL)
SCHEMATIC08/CAN3_RS: R31.1 U7.8(Rs)
SCHEMATIC08/RS485_A: JP1.1 R28.2 U6.6(A)
SCHEMATIC08/RS485_B: JP1.2 R28.1 U6.7(B)
Schematic9/12M_I: C25.1 U8.30(XT_IN) X2.1(XIN)
Schematic9/12M_O: C26.1 U8.29(XT_OUT) X2.3(XOUT)
Schematic9/D+: R36.2 U8.12(D+)
Schematic9/D-: R35.2 U8.11(D-)
Schematic9/ICE_CLK: J3.3 U8.24(ICE_CLK)
Schematic9/ICE_DAT: J3.2 U8.23(ICE_DAT)
Schematic9/RES: C21.2 J3.4 R32.2 U8.31(RESET#)
Schematic9/UR0_RX: R34.2 U8.5(TX1/PB.5)
Schematic9/UR0_TX: R33.2 U8.4(RX1/PB.4)
USB0_DM: R38.2 R40.2 U4.61(USB0_DM)
USB0_DP: R39.2 R42.2 U4.62(USB0_DP)
USB0_ID: J4.1 U4.1(USB0_ID)
USB0_REXT: R12.1 U4.64(USB0_REXT)
VD12: C10.1 C11.1 C12.1 C13.1 CB9.1 CB10.1 CB11.1 CB12.1 CB13.1 CB14.1 CB15.1 L6.2 U4.10(VDD) U4.12(VDD) U4.31(VDD) U4.38(VDD) U4.48(VDD12) U4.58(VDD) U4.60(USB0_VDD)
VD18: C14.1 C15.1 CB16.1 CB17.1 L7.2 U4.11(MVDD) U4.39(MVDD)
VD33: C8.1 CB1.1 CB2.1 CB3.1 CB4.1 CB5.1 CB6.1 CB7.1 L4.2 L5.1 U4.9(VDDIO) U4.13(VDDIO) U4.32(VDDIO) U4.40(VDDIO) U4.54(VDDIO) U4.59(USB1_VDD33) U4.63(USB0_VDD33)
VD33_ADC: C9.1 CB8.1 L5.2 U4.18(AVDDADC)
SCHEMATIC02/N16796608: C7.1 R8.1 U3.1(EN)
SCHEMATIC02/N16796708: C1.1 R3.1 R4.2 U1.5(FB)
SCHEMATIC02/N16796752: L3.1 U3.3(SW)
SCHEMATIC02/N16796780: C5.1 R5.1 U2.1(EN)
SCHEMATIC02/N16797021: L1.1 U1.3(SW)
SCHEMATIC02/N16797059: C4.1 R6.1 R7.2 U2.5(FB)
SCHEMATIC02/N16797138: L2.1 U2.3(SW)
SCHEMATIC02/N16797165: C6.1 R9.1 R10.2 U3.5(FB)
SCHEMATIC02/N16823900: C2.1 R1.1 U1.1(EN)
SCHEMATIC05/N16858120: R15.2 SW1.3(B2)
SCHEMATIC05/N16858140: R16.2 SW1.4(B1)
SCHEMATIC05/N16866202: LED1.1 R13.1
SCHEMATIC05/N16866352: LED2.1 R14.1
SCHEMATIC05/N16866847: C18.1 Q1.BASE R20.1
Schematic9/N16765798: C23.2 U8.6(LDO_OUT)
Schematic9/N16779489: C28.1 CON2.6(\) CON2.7(\) CON2.8(\) CON2.9(\)
Schematic9/N16779536: CON2.2(D-) R35.1
Schematic9/N16779538: CON2.3(D+) R36.1
Schematic9/N16797547: CON2.5(GND) L8.2
Schematic9/N17128688: C20.1 U8.10(USB_LDO_OUT)
Schematic10/N16470732: CON4.5(GND) L10.2
Schematic10/N16470772: C32.1 CON4.6(\) CON4.7(\) CON4.8(\) CON4.9(\)
Schematic10/N16470806: CON4.2(D-) R40.1
Schematic10/N16470810: CON4.3(D+) R42.1
Schematic10/N16472794: CON3.4(GND) L9.2
Schematic10/N16472826: C29.2 CON3.1(VBUS) F1.1
Schematic10/N16472846: CON3.2(D-) R38.1
Schematic10/N16472850: CON3.3(D+) R39.1
Schematic10/N16472878: C30.1 CON3.5(Shield) CON3.6(Shield)

Not connected (* = marked no-connect by the designer): CON1 3 4 15 17 18; CON2 4(ID); CON4 4(ID); U7 5(Vref)*; U8 1(INT0/PB.14)* 2(I2C1_SCL/PA.11)* 3(I2C1_SDA/PA.10)* 13(MOSI0_0/PC.3)* 14(MISO0_0/PC.2)* 15(SPI0_CLK/PC.1)* 16(SPI0_CS0/PC.0)* 17(MOSI1_1/PC.13)* 18(MISO1_1/PC.12)* 19(MOSI1_0/PC.11)* 20(MISO1_0/PC.10)* 21(SPI1_CLK/PC.9)* 22(SPI1_CS0/PC.8)* 26(SPI2_CLK/PD.1)* 27(MISO2_0/PD.2)* 28(MOSI2_0/PD.3)*

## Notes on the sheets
sheet 3
- 1
- VCOM
sheet 4
- PG1
- PG0
- Booting from
- ON(0)
- ON(0)
- USB
- OFF(1)
- OFF(1)
- QSPI Flash_0
- Power On Setting
- V33
- TRST
- LED1
- LED2
- TDI
- TMS
- TCK
- TDO
- RES
- VSS
- 12MHz
- Reset
- K1
sheet 5
- USB0_H
- USB0_H
- USB0_D
sheet 7
- Ethernet
- V33
- V33
- PF9
- PF8
- PF5
- PF7
- PF4
- PF6
- PF3
- PF2
- PF1
- PF0
- RES
- VSS
- VSS
- V18
- V33
- PB6
- PB4
- PC3
- PC4
- PC5
- PC6
- PC8
- PC9
- PC10
- VSS
sheet 8
- RS485
- H
- CAN
- L
sheet 10
- PIN
- FUNCTION
- PIN
- FUNCTION
- PIN
- FUNCTION
- PIN
- FUNCTION
- PIN
- FUNCTION
- PIN
- FUNCTION
- PIN
- FUNCTION
- PA0
- CAN3_RXD
- PB4
- I2C1_SCL
- PC3
- LED_G
- PD2
- QSPI0_SS0
- PE11
- USB0_VBUSVLD
- PF0
- RMII1_RXERR
- PG0
- CFG[0]
- PA1
- CAN3_TXD
- PB6
- I2C1_SDA
- PC4
- SPI0_DO
- PD3
- QSPI0_CLK
- PF1
- RMII1_CRSDV
- PA2
- JTAG1_TDO
- PC5
- SPI0_SS0
- PD4
- QSPI0_DO
- PF2
- RMII1_RXD1
- PG1
- CFG[1]
- PA3
- JTAG1_TCK
- PC6
- SPI0_CLK
- PD5
- QSPI0_DI
- PF3
- RMII1_RXD0
- PA4
- JTAG1_TMS
- PC8
- SPI0_DI
- PF4
- RMII1_REFCLK
- PA5
- JTAG1_TDI
- PC9
- UART4_TXD
- PF5
- RMII1_TXEN
- PA6
- JTAG1_nTRST
- PC10
- UART4_RXD
- PF6
- RMII1_TXD1
- PC11
- LED_G
- PF7
- RMII1_TXD0
- PC12
- UART8_TXD
- PF8
- RMII1_MDIO
- PC13
- UART8_RXD
- PF9
- RMII1_MDC
- PC14
- UART8_RTS
- PF11
- UART0_RXD
- PC15
- button
- PF12
- UART0_TXD
sheet 11
- V33
- V50
- V12
- V18
